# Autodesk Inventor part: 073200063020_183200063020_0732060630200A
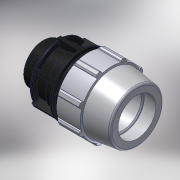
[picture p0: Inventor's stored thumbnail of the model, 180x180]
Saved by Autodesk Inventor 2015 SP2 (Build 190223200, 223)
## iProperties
Created: 2017-02
Part Number: 073200063020_183200063020_0732060630200A
Material: PVC-Piping
Description: 073200063020_183200063020_0732060630200A
Document SubType Name: Modeling
Designer: KIM
Mass: 92.6774 g
Surface Area: 199.44 cm^2
Volume: 66.1981 cm^3
Density: 1.4 g/cm^3
Appearance: PTFE
Author: Кирилл
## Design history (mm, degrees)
derived "07320.ipt"
feature "Solid1::07320.ipt"
tag "TaggingFeature1"
body "Solid1"
other parameters: "d2" = 63, "d4" = 22.28571, "d5" = 40.56, "d7" = 113, "d8" = 84.75, "d9" = 22.28571, "d11" = 4.45714, "d12" = 90.4, "d13" = 120 deg, "d14" = 88.2, "d15" = 8 deg, "d16" = 101.7, "d18" = 3.15, "d19" = 35 deg, "d20" = 17.5 deg, "d21" = 105.09, "d23" = 0, "d25" = 360 deg, "d27" = 2.26, "d34" = 5.65, "d36" = 0, "d42" = 40.56, "d43" = 3.39, "d46" = 1.89, "d49" = 123, "d51" = 156, "d53" = 1.26, "d55" = 360 deg, "d57" = 67, "d58" = 46.9, "d59" = 31.2, "d62" = 16, "d63" = 60.3, "d64" = 2, "d_" = 63, "E_" = 113, "H_" = 156, "l_" = 123, "L_" = 16, "B_" = 67
